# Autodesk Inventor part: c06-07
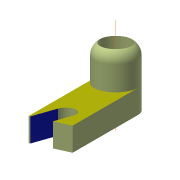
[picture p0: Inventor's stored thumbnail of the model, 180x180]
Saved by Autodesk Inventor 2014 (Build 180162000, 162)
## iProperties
Created: 2013-03
Part Number: c06-07
Material: Aluminum 6061
Document SubType Name: Modeling
Designer: Thom Tremblay
Density: 2.71 g/cm^3
Appearance: Zinc Chromate 2
Author: Thom Tremblay
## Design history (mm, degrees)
sketch "Sketch1"
  geometry: L1 (0, -12.5)-(60, -12.5); L2 (60, -12.5)-(60, 12.5); L3 (60, 12.5)-(0, 12.5); L4 (0, 12.5)-(0, -12.5); 2 further points
  constraints: 8 end point, 2 parallel, 1 coincident, 1 horizontal, 1 midpoint, 1 perpendicular
  dimensions: "d1" = 25 distance of L2.end L1.end; "d2" = 60 distance of L2.end L3.end
extrude "Base" new body sketch "Sketch1" distance "d3" = 14; taper "d4" = 0 deg
sketch "Sketch2"
  geometry: C1 r 12.5 at (0, 0); 1 further point
  constraints: 1 centre point, 1 coincident
extrude "Boss" join sketch "Sketch2" distance "d5" = 35; taper "d6" = 0 deg
sketch "Sketch3"
  geometry: L1 (-60, 12.5)-(-60, -12.5) reference; L2 (-60, -6)-(-60, 6); L3 (-43.948, 5.638)-(-60, 11.481); L4 (-48.052, -5.638)-(-60, -1.289); L5 (-60, 11.481)-(-60, -1.289); A1 r 6 centre (-46, 0) between (-43.948, 5.638) and (-48.052, -5.638); 2 further points
  constraints: 8 end point, 3 midpoint, 2 point on circle, 2 point on line, 2 tangent, 1 centre point, 1 collinear, 1 horizontal alignment, 1 parallel
  dimensions: "d8" = 12 diameter of A1; "d20" = 20 dimension on A1 L1; "d27" = 70 deg angle of L1 L3
extrude "Slot" cut sketch "Sketch3" stored distance "d9" = 24; taper "d10" = 0 deg
hole "Hole1" diameter "d13" = 11; stored, may be unused: countersink angle "d17" = 90 deg, drill point angle "d19" = 118 deg; dims "d11" = 10, "d12" = 10, "d14" = 6, "d15" = 18, "d16" = 11, "d18" = 8
fillet "Fillet1" dims "d26" = 8
node "Midplane between faces"
node "Normal to Edge at Point"
node "Offset Plane"
  node "Tangent Plane"
sketch "Sketch4"
  geometry: L1 (0, 0)-(-60, 0) reference; L2 (-14, 0)-(-18.341, 24.62)
  constraints: 2 end point, 1 point on line
  dimensions: "d21" = 25 distance of L2.start L2.end; "d22" = 80 deg angle of L1 L2; "d23" = 14 distance of L1.start L2.start
node "Plane at Angle on Sketch"
sketch "Sketch5"
  geometry: L1 (0, 0)-(-19.151, 16.07); L2 (0, 0)-(25, 0); C1 r 9 at (0, 0) reference; C2 r 5.5 at (0, 0) reference
  constraints: 4 end point, 1 equal length, 1 horizontal
  dimensions: "d24" = 25 distance of L1.start L1.end; "d25" = 140 deg angle of L2 L1
node "Plane using Sketch as Axis"
body "Solid1"
workaxis "Work Axis1"
node "Plane at Angle"
other parameters: "d28" = 30 deg, "d29" = 15, "d30" = 90 deg
